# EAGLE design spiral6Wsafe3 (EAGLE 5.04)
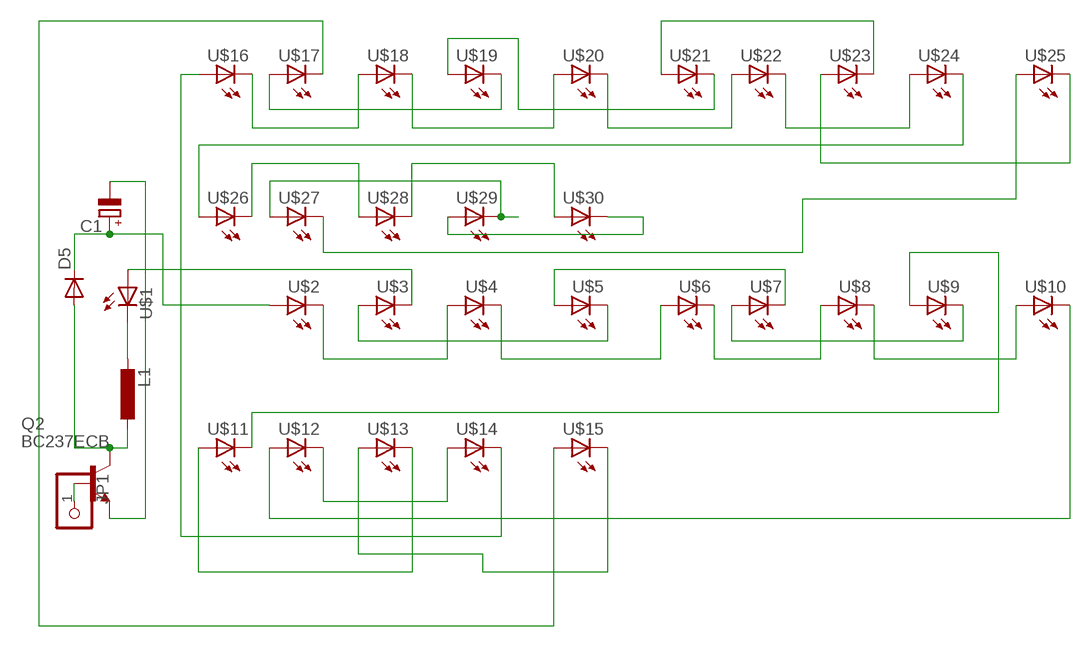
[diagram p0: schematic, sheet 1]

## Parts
C1  CPOL-EUE5-6  [E5-6]
D5  DIODE-D-5  [D-5]
JP1  PINHD-1X1  [1X01]
L1  L-EU0207/10  [0207/10]
Q2  BC237ECB  [TO92-BCE]
U$1  LED5MM  [LED5MM]
U$2  LED5MM  [LED5MM]
U$3  LED5MM  [LED5MM]
U$4  LED5MM  [LED5MM]
U$5  LED5MM  [LED5MM]
U$6  LED5MM  [LED5MM]
U$7  LED5MM  [LED5MM]
U$8  LED5MM  [LED5MM]
U$9  LED5MM  [LED5MM]
U$10  LED5MM  [LED5MM]
U$11  LED5MM  [LED5MM]
U$12  LED5MM  [LED5MM]
U$13  LED5MM  [LED5MM]
U$14  LED5MM  [LED5MM]
U$15  LED5MM  [LED5MM]
U$16  LED5MM  [LED5MM]
U$17  LED5MM  [LED5MM]
U$18  LED5MM  [LED5MM]
U$19  LED5MM  [LED5MM]
U$20  LED5MM  [LED5MM]
U$21  LED5MM  [LED5MM]
U$22  LED5MM  [LED5MM]
U$23  LED5MM  [LED5MM]
U$24  LED5MM  [LED5MM]
U$25  LED5MM  [LED5MM]
U$26  LED5MM  [LED5MM]
U$27  LED5MM  [LED5MM]
U$28  LED5MM  [LED5MM]
U$29  LED5MM  [LED5MM]
U$30  LED5MM  [LED5MM]

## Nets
N$2: U$2.K(C) U$4.A
N$3: U$4.K(C) U$6.A
N$4: U$6.K(C) U$8.A
N$5: U$8.K(C) U$10.A
N$6: U$1.A U$3.K(C)
N$7: U$3.A U$5.K(C)
N$8: U$5.A U$7.K(C)
N$9: U$7.A U$9.K(C)
N$10: U$10.K(C) U$12.A
N$11: U$12.K(C) U$14.A
N$12: U$14.K(C) U$16.A
N$13: U$16.K(C) U$18.A
N$14: U$18.K(C) U$20.A
N$15: U$20.K(C) U$22.A
N$16: U$22.K(C) U$24.A
N$17: U$24.K(C) U$26.A
N$18: U$26.K(C) U$28.A
N$19: U$28.K(C) U$30.A
N$20: U$29.A U$30.K(C)
N$21: D5.A L1.1 Q2.C
N$22: L1.2 U$1.K(C)
N$23: U$27.A U$29.K(C)
N$24: U$25.A U$27.K(C)
N$26: C1.+ D5.C U$2.A
N$27: U$9.A U$11.K(C)
N$28: C1.- Q2.B(E)
N$29: U$11.A U$13.K(C)
N$30: U$13.A U$15.K(C)
N$31: U$15.A U$17.K(C)
N$32: U$17.A U$19.K(C)
N$33: U$19.A U$21.K(C)
N$34: U$21.A U$23.K(C)
N$35: U$23.A U$25.K(C)
N$36: JP1.1 Q2.E(B)

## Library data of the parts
C1 = rcl-2:CPOL-EU: POLARIZED CAPACITOR, European symbol
D5 = diode-1:DIODE-: DIODE
JP1 = pinhead:PINHD-1X1: PIN HEADER
L1 = rcl-2:L-EU: INDUCTOR, European symbol
Q2 = transistor-npn:BC237: NPN Transistor
U$1-U$30 = led(2):LED: LED

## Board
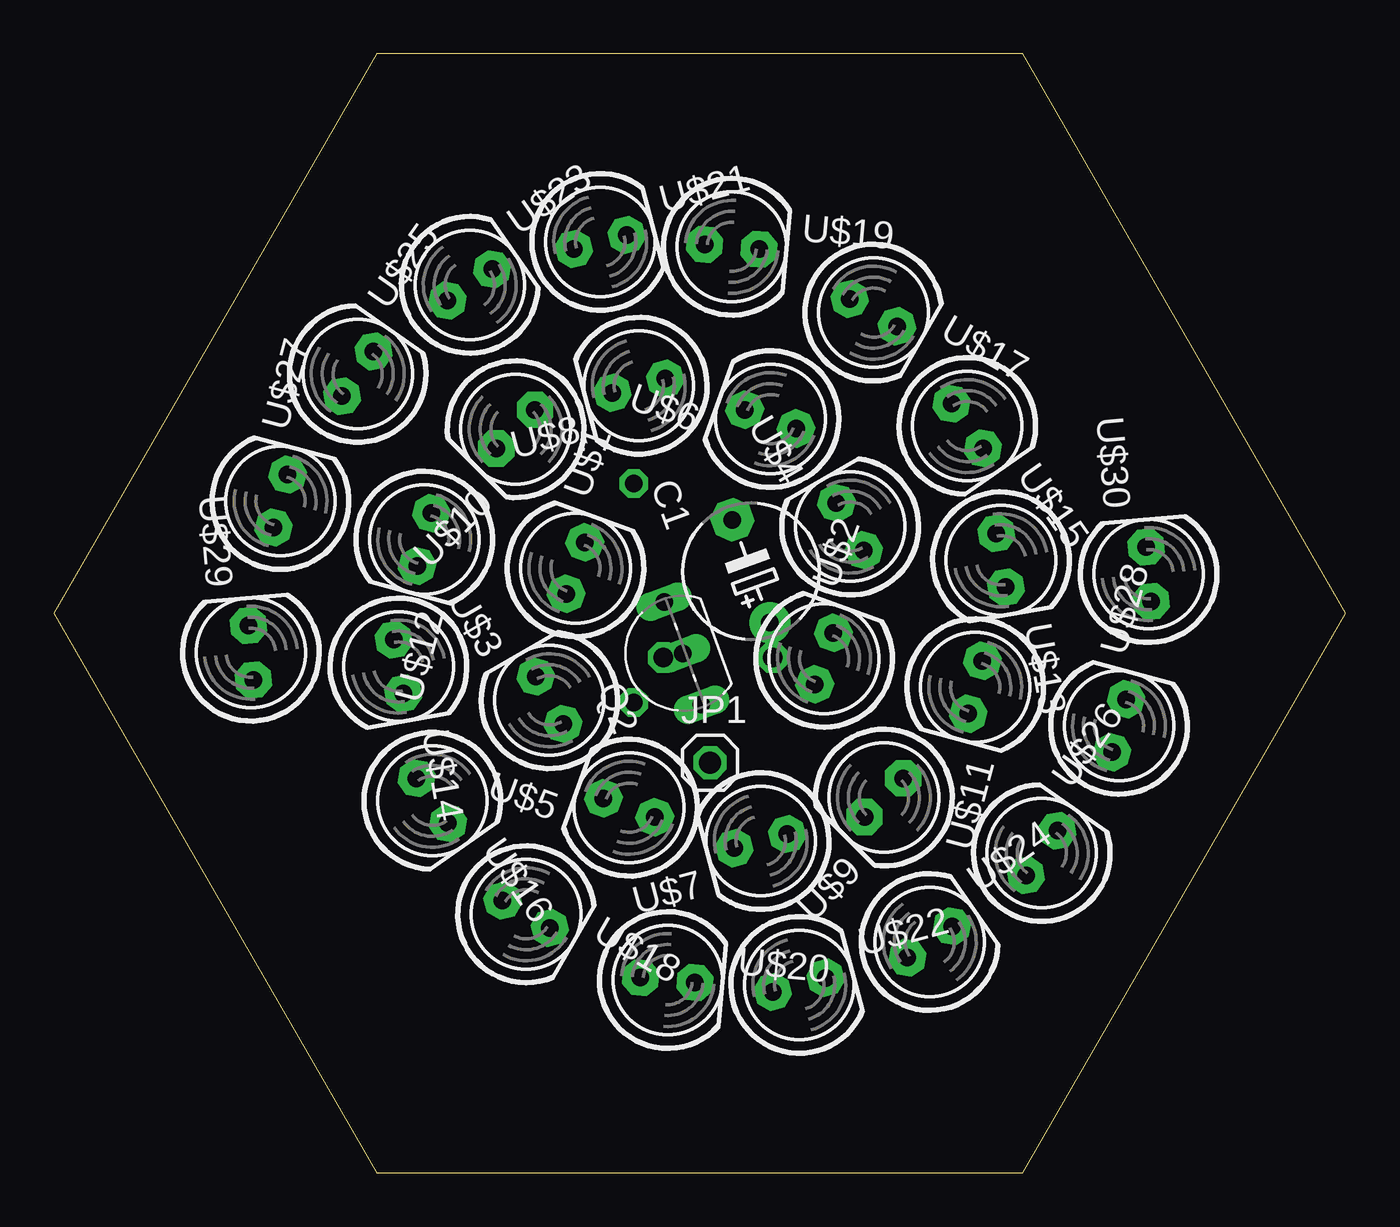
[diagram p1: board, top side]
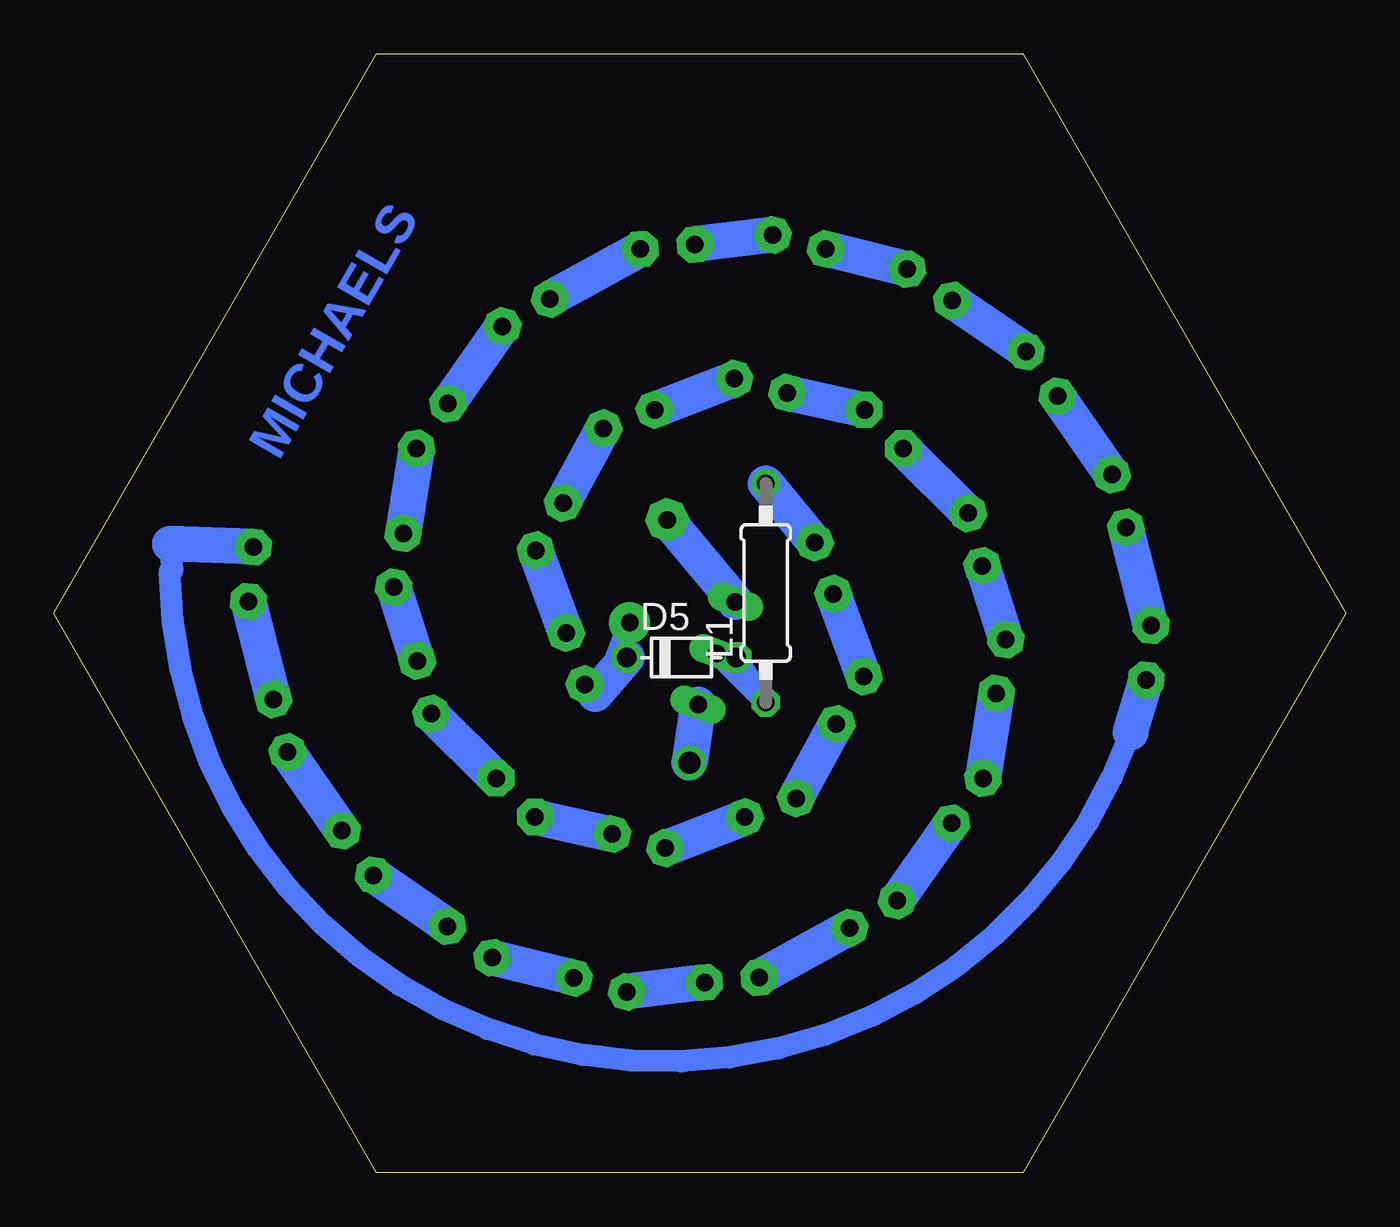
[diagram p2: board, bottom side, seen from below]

Size 60 x 51.96 mm. Coordinates in mm from the lower left corner, seen from the top.
Outline: 15,0 45,0 60,25.98 45,51.96 15,51.96 0,25.98 15,0
Copper layers (1*16): Top 0.035mm / dielectric 1.5mm / Bottom 0.035mm
Design rules "default": minimum track width 10mil, minimum drill 24mil, track to track 8mil, track to pad 8mil, pad to pad 8mil, via to via 8mil, smd to smd 8mil, copper to edge 40mil, drill to drill 8mil, minimum pad ring 10mil, minimum via ring 8mil, stop-mask expansion 4mil, vias tented up to drill 0mil, thermal gap 10mil

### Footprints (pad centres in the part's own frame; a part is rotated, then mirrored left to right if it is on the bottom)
E5-6 = drill 0.813 pad 1.905 round: + -2.54,0 | drill 0.813 pad 1.905 octagon: - 2.54,0
D-5 = drill 0.9 octagon: A 2.54,0; C -2.54,0
1X01 = drill 1.016 octagon: 1 0,0
0207/10 = drill 0.813 octagon: 1 -5.08,0; 2 5.08,0
TO92-BCE = drill 0.813 long: B 2.54,0; C 0,0; E -2.54,0
LED5MM = drill 0.813 pad 1.676 octagon: A -1.27,0; K 1.27,0

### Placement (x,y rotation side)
C1  32.38,27.94 110 top
D5  30.85,23.93 0 bottom
JP1  30.48,19.05 0 top
L1  26.93,26.93 90 bottom
Q2  29.21,24.13 110 top
U$1  24.23,28.08 70 top
U$2  35.77,23.88 70 top
U$3  23.02,21.95 120 top
U$4  36.98,30.01 120 top
U$5  26.72,16.96 160 top
U$6  33.28,35 160 top
U$7  32.83,15.41 195 top
U$8  27.17,36.55 195 top
U$9  38.55,17.43 225 top
U$10  21.45,34.53 225 top
U$11  42.8,22.55 255 top
U$12  17.2,29.41 255 top
U$13  43.99,28.45 280 top
U$14  16.01,23.51 280 top
U$15  42.42,34.68 305 top
U$16  17.58,17.28 305 top
U$17  38.06,39.95 330 top
U$18  21.94,12.01 330 top
U$19  31.49,43 355 top
U$20  28.51,8.96 355 top
U$21  25.38,43.23 14.9 top
U$22  34.62,8.73 14.9 top
U$23  19.32,41.23 35 top
U$24  40.68,10.73 35 top
U$25  14.12,37.1 54.9 top
U$26  45.88,14.86 54.9 top
U$27  10.53,31.2 75 top
U$28  49.47,20.76 75 top
U$29  9.15,24.16 95 top
U$30  50.85,27.8 95 top

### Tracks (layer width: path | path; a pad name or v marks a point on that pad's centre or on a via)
N$2
  Bottom 1.676: U$2.K U$4.A
N$3
  Bottom 1.676: U$4.K U$6.A
N$4
  Bottom 1.676: U$6.K U$8.A
N$5
  Bottom 1.676: U$8.K U$10.A
N$6
  Bottom 1.676: U$3.K U$1.A
N$7
  Bottom 1.676: U$5.K U$3.A
N$8
  Bottom 1.676: U$7.K U$5.A
N$9
  Bottom 1.676: U$9.K U$7.A
N$10
  Bottom 1.676: U$10.K U$12.A
N$11
  Bottom 1.676: U$12.K U$14.A
N$12
  Bottom 1.676: U$14.K U$16.A
N$13
  Bottom 1.676: U$16.K U$18.A
N$14
  Bottom 1.676: U$18.K U$20.A
N$15
  Bottom 1.676: U$20.K U$22.A
N$16
  Bottom 1.676: U$22.K U$24.A
N$17
  Bottom 1.676: U$24.K U$26.A
N$18
  Bottom 1.676: U$26.K U$28.A
N$19
  Bottom 1.676: U$28.K U$30.A
N$20
  Bottom 0.254: 54.61,27.94 54.5,28
  Bottom 1.016: 10,20.46 arc160 54.61,27.94 | 54.61,29.21 54.5,28
  Bottom 1.676: 10,20.46 U$29.A | U$30.K 54.61,29.21
N$21
  Bottom 1.016: Q2.C L1.1 D5.A
N$22
  Bottom 1.676: U$1.K L1.2
N$23
  Bottom 1.676: U$29.K U$27.A
N$24
  Bottom 1.676: U$27.K U$25.A
N$26
  Bottom 1.016: U$2.A 34.84,22.24 34.29,22.86 C1.+
  Bottom 1.676: D5.C 34.84,22.24
N$27
  Bottom 1.676: U$11.K U$9.A
N$28
  Bottom 1.676: C1.- Q2.B
N$29
  Bottom 1.676: U$13.K U$11.A
N$30
  Bottom 1.676: U$15.K U$13.A
N$31
  Bottom 1.676: U$17.K U$15.A
N$32
  Bottom 1.676: U$19.K U$17.A
N$33
  Bottom 1.676: U$21.K U$19.A
N$34
  Bottom 1.676: U$23.K U$21.A
N$35
  Bottom 1.676: U$25.K U$23.A
N$36
  Bottom 1.676: Q2.E JP1.1

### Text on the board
Bottom: MICHAELS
